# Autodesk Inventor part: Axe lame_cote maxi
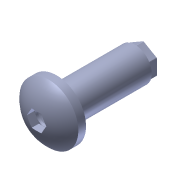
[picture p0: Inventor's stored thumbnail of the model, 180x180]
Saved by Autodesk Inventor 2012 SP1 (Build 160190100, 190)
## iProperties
Created: 2014-12
Part Number: Axe lame_cote maxi
Material: Default
Document SubType Name: Modeling
Designer: Bruno
Density: 1 g/cm^3
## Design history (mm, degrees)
node "Axe lame_cote maxi1"
node "Axe lame_cote maxi"
node "Base1"
